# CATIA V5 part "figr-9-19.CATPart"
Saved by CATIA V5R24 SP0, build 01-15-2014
Part number: Part3
Bounding box of the stored display mesh (mm): x -17.259 to 115.9, y -137.259 to 0, z -17.083 to 17.083
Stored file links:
  D:\KAVITA\CATIA V5-6R2014 Project_ Kavita\CATIA V5-6R2014_partfiles\Partfiles\c09_catia_v5-6r2014_prt\figr-9-19.CATPart
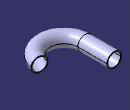
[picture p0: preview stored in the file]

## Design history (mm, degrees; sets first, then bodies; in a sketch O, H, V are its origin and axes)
Body1 (main body)
  Sketch1 on zx-plane, origin (0, 0, 0), H (-1, 0, 0), V (0, 0, 1)
    circle A1 centre (0, 0) radius 17.2586
  Sketch2 on xy-plane, origin (0, 0, 0), H (1, 0, 0), V (0, 1, 0)
    line L1 (0, 0) -> (0, -70)
    arc A1 centre (50, -70) radius 50 from (0, -70) to (50, -120) ccw
    arc A2 centre (50, -70) radius 50 from (50, -120) to (98.9898, -80) ccw
    vertical: L1 V
    tangency: A1 L1, A2 L1, A2 A1
  Rib1: profile Sketch1, centre curve Sketch2, thin wall 2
